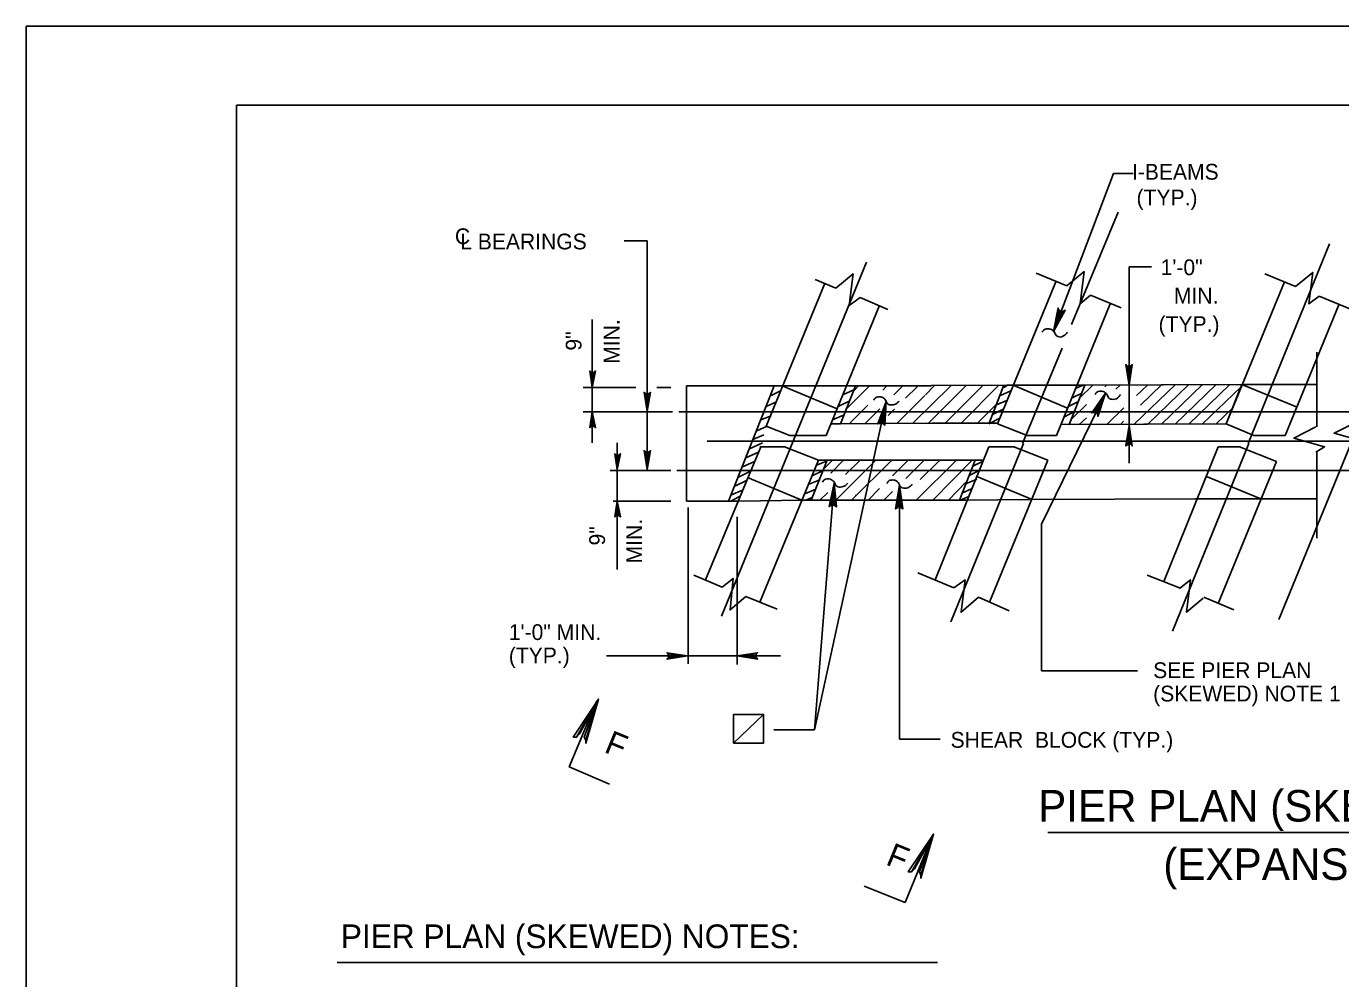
# Model space of a CAD drawing. Extents: x 638091 to 638946, y 298288 to 298882.
# Drawn here: x 638090.6 to 638340.6, y 298700.4 to 298881.5 of the extents above; entities that cross this region are included whole.
import ezdxf

# ---------------------------------------------------------------- set-up
doc = ezdxf.new("R2010")
doc.units = 0
for name, color, linetype in [('1', 7, 'Continuous'), ('2', 7, 'Continuous'), ('PLT-BNDY', 7, 'Continuous')]:
    doc.layers.add(name, color=color, linetype=linetype)

msp = doc.modelspace()

# ---------------------------------------------------------------- linework, layer by layer
at = {"layer": '1'}
for p, q in [((638290.98, 298810.87), (638293.45, 298813.25)), ((638295.72, 298812.94), (638296.06, 298813.27)), ((638297.84, 298812.49), (638298.66, 298813.28)), ((638301.29, 298805.81), (638309.08, 298813.33)), ((638301.75, 298811.26), (638303.87, 298813.31)), ((638302.48, 298809.46), (638306.48, 298813.32)), ((638303.9, 298805.82), (638311.69, 298813.35)), ((638306.5, 298805.83), (638314.29, 298813.36)), ((638309.1, 298805.85), (638316.9, 298813.37)), ((638311.71, 298805.86), (638319.5, 298813.38)), ((638314.31, 298805.87), (638321.58, 298812.89)), ((638240.51, 298747.71), (638254.12, 298810.14)), ((638289.35, 298806.79), (638292.22, 298809.56)), ((638296.08, 298805.78), (638299.34, 298808.93)), ((638316.92, 298805.89), (638319.95, 298808.82)), ((638290.87, 298805.76), (638292.21, 298807.05)), ((638298.69, 298805.79), (638299.3, 298806.39)), ((638244.27, 298794.62), (638240.51, 298747.71))]:
    msp.add_line(p, q, dxfattribs=at)
for points in [[(638291.93, 298813.25), (638288.93, 298805.75), (638318.78, 298805.9), (638321.78, 298813.4)], [(638225.11, 298745.15), (638230.77, 298745.15), (638230.77, 298750.63), (638225.11, 298750.63)], [(638225.11, 298745.15), (638230.77, 298750.63), (638230.77, 298745.15)]]:
    msp.add_lwpolyline(points, close=True, dxfattribs=at)
at = {"layer": '2'}
for p, q in [((638130.58, 298302.5), (638130.58, 298866.5)), ((638130.58, 298866.5), (638916.58, 298866.5)), ((638328.83, 298768.7), (638365.58, 298858.55)), ((638297.34, 298853.53), (638285.93, 298823.45)), ((638301.09, 298853.53), (638297.34, 298853.53)), ((638289.38, 298824.8), (638298.24, 298846.18)), ((638204.33, 298840.7), (638208.68, 298840.7)), ((638208.68, 298808.3), (638208.68, 298840.7)), ((638322.98, 298802.15), (638338.43, 298840.1)), ((638236.13, 298801.85), (638250.38, 298836.65)), ((638300.33, 298813.25), (638300.33, 298835.74)), ((638304.57, 298835.74), (638300.33, 298835.74)), ((638231.33, 298805.45), (638242.43, 298832.45)), ((638244.53, 298831.7), (638240.63, 298833.35)), ((638275.28, 298805.9), (638286.38, 298832.9)), ((638288.48, 298832.15), (638282.63, 298834.55)), ((638318.78, 298805.9), (638329.88, 298832.9)), ((638331.98, 298832), (638326.13, 298834.4)), ((638254.43, 298827.65), (638249.18, 298829.9)), ((638298.83, 298827.95), (638292.98, 298830.35)), ((638343.38, 298827.35), (638336.48, 298830.2)), ((638252.78, 298828.25), (638242.73, 298803.65)), ((638296.73, 298828.7), (638286.53, 298803.65)), ((638340.23, 298828.55), (638330.03, 298803.65)), ((638198.24, 298812.95), (638198.24, 298825.75)), ((638280.08, 298802.15), (638287.58, 298820.3)), ((638336.03, 298805.3), (638336.03, 298819.55)), ((638196.47, 298812.8), (638206.51, 298812.8)), ((638198.24, 298808.15), (638198.24, 298812.95)), ((638210.52, 298812.8), (638213.18, 298812.8)), ((638216.18, 298791.2), (638216.18, 298813.1)), ((638235.08, 298813.1), (638216.18, 298813.1)), ((638224.13, 298791.2), (638232.83, 298813.1)), ((638232.23, 298811.3), (638234.03, 298812.2)), ((638244.83, 298808.75), (638234.33, 298813.1)), ((638246.93, 298813.1), (638234.78, 298813.1)), ((638245.43, 298805.9), (638248.28, 298813.1)), ((638246.03, 298811.45), (638247.98, 298812.35)), ((638246.48, 298808.6), (638250.98, 298813.1)), ((638246.48, 298813.1), (638262.7, 298813.1)), ((638247.98, 298812.2), (638248.88, 298813.1)), ((638253.49, 298812.3), (638254.28, 298813.1)), ((638255.6, 298811.42), (638257.28, 298813.1)), ((638257.81, 298810.77), (638260.06, 298813.02)), ((638259.22, 298806.03), (638266.43, 298813.1)), ((638261.59, 298811.4), (638263.28, 298813.1)), ((638262.17, 298805.99), (638269.43, 298813.25)), ((638262.78, 298813.18), (638277.08, 298813.25)), ((638265.38, 298806.05), (638272.58, 298813.25)), ((638268.38, 298806.05), (638275.58, 298813.25)), ((638276.48, 298813.25), (638273.69, 298806.04)), ((638277.83, 298812.2), (638275.88, 298811.3)), ((638277.23, 298813.25), (638276.48, 298812.8)), ((638277.08, 298813.25), (638278.28, 298813.25)), ((638291.78, 298813.25), (638278.28, 298813.25)), ((638288.63, 298808.9), (638278.28, 298813.25)), ((638288.93, 298805.75), (638291.93, 298813.25)), ((638291.63, 298813.25), (638290.28, 298812.65)), ((638290.73, 298813.25), (638322.23, 298813.4)), ((638300.33, 298805.6), (638300.33, 298813.25)), ((638332.28, 298809.05), (638321.78, 298813.4)), ((638334.38, 298813.4), (638322.23, 298813.4)), ((638336.03, 298813.4), (638334.08, 298813.4)), ((638231.33, 298809.2), (638233.28, 298810.1)), ((638244.98, 298809.2), (638247.23, 298810.25)), ((638256.23, 298806.05), (638261.5, 298811.31)), ((638277.23, 298810.4), (638275.13, 298809.5)), ((638283.67, 298786.82), (638295.85, 298811.72)), ((638288.78, 298809.2), (638290.58, 298810.1)), ((638291.33, 298811.75), (638289.53, 298810.85)), ((638196.47, 298808.15), (638213.48, 298808.15)), ((638198.24, 298808.45), (638198.24, 298808.45)), ((638198.24, 298802.3), (638198.24, 298808.15)), ((638208.68, 298797.2), (638208.68, 298808.3)), ((638214.67, 298808.15), (638343.68, 298808.15)), ((638232.23, 298807.4), (638230.28, 298806.65)), ((638246.03, 298807.55), (638243.93, 298806.65)), ((638247.08, 298805.9), (638250.64, 298809.45)), ((638250.08, 298805.9), (638252.91, 298808.73)), ((638254.52, 298807.48), (638255.73, 298808.69)), ((638271.53, 298806.05), (638275.13, 298809.65)), ((638276.48, 298808.75), (638274.38, 298807.7)), ((638288.03, 298807.25), (638289.83, 298808.15)), ((638229.53, 298804.55), (638231.48, 298805.45)), ((638235.83, 298803.65), (638231.33, 298805.45)), ((638243.78, 298805.9), (638262.96, 298805.99)), ((638243.93, 298805.9), (638245.43, 298805.9)), ((638262.9, 298805.99), (638275.28, 298806.05)), ((638275.73, 298806.95), (638273.63, 298805.9)), ((638280.98, 298803.65), (638275.28, 298805.9)), ((638287.39, 298805.75), (638318.78, 298805.9)), ((638300.33, 298798.4), (638300.33, 298805.6)), ((638324.03, 298803.65), (638318.78, 298805.9)), ((638202.98, 298790.3), (638202.98, 298802.3)), ((638220.08, 298802.6), (638343.68, 298802.6)), ((638222.78, 298769.3), (638236.43, 298802.6)), ((638228.03, 298801.1), (638230.58, 298802.3)), ((638228.78, 298802.9), (638230.88, 298803.8)), ((638235.83, 298803.65), (638242.73, 298803.65)), ((638280.98, 298803.65), (638286.53, 298803.65)), ((638324.03, 298803.65), (638330.03, 298803.65)), ((638219.78, 298776.2), (638230.28, 298801.55)), ((638227.43, 298799.45), (638229.83, 298800.5)), ((638230.13, 298801.55), (638234.93, 298801.55)), ((638234.78, 298801.55), (638241.23, 298799)), ((638263.43, 298776.2), (638273.63, 298801.55)), ((638266.43, 298768.25), (638280.23, 298802.15)), ((638273.63, 298801.55), (638278.58, 298801.55)), ((638278.43, 298801.55), (638284.88, 298799)), ((638306.93, 298775.9), (638317.28, 298801.55)), ((638308.58, 298766.45), (638323.13, 298802.15)), ((638317.28, 298801.55), (638321.48, 298801.55)), ((638321.33, 298801.55), (638328.38, 298798.7)), ((638336.03, 298784.15), (638336.03, 298800.65)), ((638202.98, 298797.2), (638202.98, 298797.2)), ((638226.68, 298797.65), (638229.08, 298798.7)), ((638241.23, 298799), (638230.13, 298772)), ((638239.88, 298791.35), (638242.88, 298799)), ((638240.78, 298797.95), (638242.88, 298798.85)), ((638241.23, 298799), (638262.43, 298798.99)), ((638242.28, 298797.35), (638243.93, 298799)), ((638243.61, 298796.5), (638246.03, 298799)), ((638244.5, 298791.31), (638252.18, 298799)), ((638246.42, 298796.23), (638249.18, 298799)), ((638247.53, 298791.35), (638255.18, 298799)), ((638255.33, 298796), (638258.33, 298799)), ((638257.85, 298795.51), (638261.28, 298798.94)), ((638259.83, 298791.35), (638267.48, 298799)), ((638260.62, 298795.28), (638264.33, 298799)), ((638262.5, 298799), (638272.58, 298799)), ((638262.98, 298791.35), (638270.48, 298799)), ((638271.08, 298799), (638268.08, 298791.35)), ((638272.43, 298798.7), (638270.48, 298797.8)), ((638284.88, 298799), (638273.78, 298772)), ((638328.38, 298798.7), (638317.28, 298771.7)), ((638201.63, 298797.05), (638213.18, 298797.05)), ((638214.3, 298797.05), (638343.68, 298797.05)), ((638225.33, 298794.05), (638227.58, 298795.1)), ((638225.93, 298795.7), (638228.33, 298796.9)), ((638227.73, 298795.7), (638238.08, 298791.35)), ((638239.28, 298794.35), (638241.53, 298795.25)), ((638240.03, 298796), (638242.13, 298797.05)), ((638265.98, 298791.35), (638269.28, 298794.8)), ((638269.28, 298794.5), (638271.38, 298795.4)), ((638271.83, 298797.05), (638270.03, 298796.15)), ((638271.38, 298795.85), (638281.88, 298791.5)), ((638315.03, 298795.85), (638325.38, 298791.65)), ((638224.73, 298792.4), (638226.83, 298793.3)), ((638238.68, 298792.55), (638240.78, 298793.45)), ((638241.53, 298791.35), (638243.02, 298792.84)), ((638248.43, 298792.4), (638248.28, 298792.25)), ((638250.68, 298791.35), (638252.86, 298793.6)), ((638253.68, 298791.35), (638255.33, 298793)), ((638256.68, 298745.89), (638256.68, 298794.2)), ((638270.48, 298793.6), (638268.53, 298792.7)), ((638202.23, 298791.2), (638213.18, 298791.2)), ((638202.98, 298778.19), (638202.98, 298791.2)), ((638216.18, 298791.2), (638225.93, 298791.2)), ((638216.48, 298760.26), (638216.48, 298790)), ((638224.58, 298791.2), (638226.23, 298792.1)), ((638226.23, 298791.2), (638238.23, 298791.35)), ((638238.23, 298791.35), (638269.73, 298791.35)), ((638238.83, 298791.35), (638240.18, 298791.95)), ((638269.88, 298792.1), (638268.23, 298791.35)), ((638269.28, 298791.35), (638281.43, 298791.5)), ((638281.88, 298791.5), (638313.38, 298791.65)), ((638312.93, 298791.65), (638325.08, 298791.65)), ((638325.08, 298791.65), (638327.93, 298791.65)), ((638327.63, 298791.65), (638336.03, 298791.65)), ((638225.78, 298760.11), (638225.78, 298788.2)), ((638283.67, 298758.92), (638283.67, 298786.82)), ((638260.13, 298777.55), (638267.03, 298774.7)), ((638217.53, 298777.1), (638222.93, 298774.85)), ((638303.78, 298777.1), (638309.93, 298774.7)), ((638227.43, 298773.05), (638233.43, 298770.65)), ((638271.68, 298772.9), (638277.53, 298770.35)), ((638314.58, 298772.9), (638320.28, 298770.5)), ((638200.96, 298761.76), (638216.33, 298761.76)), ((638216.48, 298761.76), (638225.78, 298761.76)), ((638225.78, 298761.76), (638234.03, 298761.76)), ((638283.67, 298758.92), (638301.94, 298758.92)), ((638193.86, 298740.63), (638199.11, 298753.23)), ((638240.51, 298747.71), (638232.79, 298747.71)), ((638264.41, 298745.89), (638256.68, 298745.89)), ((638193.86, 298740.63), (638201.51, 298737.33)), ((638257.74, 298714.83), (638262.99, 298727.73)), ((638284.85, 298728.2), (638389.85, 298728.2)), ((638249.94, 298717.98), (638257.74, 298714.83)), ((638149.7, 298703.43), (638263.88, 298703.43))]:
    msp.add_line(p, q, dxfattribs=at)
for points in [[(638288.48, 298832.15), (638291.78, 298834.85), (638291.03, 298828.7), (638292.98, 298830.35)], [(638331.98, 298832), (638335.28, 298834.7), (638334.53, 298828.7), (638336.48, 298830.2)], [(638244.53, 298831.7), (638247.83, 298834.4), (638247.08, 298828.4), (638249.18, 298829.9)], [(638286.83, 298827.65), (638287.13, 298827.5), (638285.93, 298823.45), (638286.83, 298827.65), (638286.83, 298827.95), (638285.93, 298823.45), (638287.58, 298827.2), (638287.88, 298827.35), (638285.93, 298823.45), (638288.18, 298827.5), (638287.88, 298827.35)], [(638198.69, 298815.8), (638198.39, 298815.65), (638198.24, 298812.8), (638198.69, 298815.8), (638198.84, 298815.95), (638198.24, 298812.8), (638198.09, 298815.65), (638197.94, 298815.8), (638198.24, 298812.8), (638197.79, 298815.95), (638197.94, 298815.8)], [(638300.78, 298817), (638300.48, 298816.85), (638300.33, 298813.25), (638300.78, 298817), (638300.93, 298817.15), (638300.33, 298813.25), (638300.18, 298816.85), (638299.88, 298816.85), (638300.33, 298813.25), (638299.73, 298817.15), (638299.88, 298816.85)], [(638209.13, 298811.75), (638208.83, 298811.6), (638208.68, 298808.3), (638209.13, 298811.75), (638209.28, 298811.9), (638208.68, 298808.3), (638208.53, 298811.6), (638208.23, 298811.75), (638208.68, 298808.3), (638208.08, 298811.9), (638208.23, 298811.75)], [(638252.7, 298805.99), (638253.02, 298806.08), (638254.12, 298810.14), (638252.7, 298805.99), (638252.52, 298805.87), (638254.12, 298810.14), (638253.46, 298805.99), (638253.73, 298805.78), (638254.12, 298810.14), (638253.85, 298805.61), (638253.73, 298805.78)], [(638293.44, 298808.05), (638293.77, 298808.07), (638295.85, 298811.75), (638293.44, 298808.05), (638293.24, 298807.98), (638295.85, 298811.75), (638294.18, 298807.89), (638294.4, 298807.64), (638295.85, 298811.75), (638294.42, 298807.3), (638294.4, 298807.64)], [(638197.94, 298805.3), (638198.09, 298805.45), (638198.24, 298808.15), (638197.94, 298805.3), (638197.79, 298805.15), (638198.24, 298808.15), (638198.39, 298805.45), (638198.69, 298805.3), (638198.24, 298808.15), (638198.84, 298805.15), (638198.69, 298805.3)], [(638299.88, 298801.85), (638300.18, 298802), (638300.33, 298805.6), (638299.88, 298801.85), (638299.73, 298801.7), (638300.33, 298805.6), (638300.48, 298802), (638300.78, 298802), (638300.33, 298805.6), (638300.93, 298801.7), (638300.78, 298802)], [(638299.88, 298801.85), (638300.18, 298802), (638300.33, 298805.6), (638299.88, 298801.85), (638299.73, 298801.7), (638300.33, 298805.6), (638300.48, 298802), (638300.78, 298802), (638300.33, 298805.6), (638300.93, 298801.7), (638300.78, 298802)], [(638335.88, 298805.3), (638331.68, 298803.2), (638337.53, 298801.55), (638335.88, 298800.5)], [(638343.53, 298806.2), (638339.33, 298804.1), (638345.18, 298802.45), (638343.53, 298801.4)], [(638203.43, 298800.05), (638203.13, 298799.9), (638202.98, 298797.2), (638203.43, 298800.05), (638203.58, 298800.2), (638202.98, 298797.2), (638202.83, 298799.9), (638202.68, 298800.05), (638202.98, 298797.2), (638202.53, 298800.2), (638202.68, 298800.05)], [(638209.13, 298800.65), (638208.83, 298800.5), (638208.68, 298797.2), (638209.13, 298800.65), (638209.28, 298800.8), (638208.68, 298797.2), (638208.53, 298800.5), (638208.23, 298800.65), (638208.68, 298797.2), (638208.08, 298800.8), (638208.23, 298800.65)], [(638243.47, 298790.31), (638243.77, 298790.44), (638244.27, 298794.62), (638243.47, 298790.31), (638243.31, 298790.16), (638244.27, 298794.62), (638244.22, 298790.42), (638244.51, 298790.26), (638244.27, 298794.62), (638244.66, 298790.1), (638244.51, 298790.26)], [(638256.08, 298789.85), (638256.38, 298790), (638256.68, 298794.2), (638256.08, 298789.85), (638255.93, 298789.7), (638256.68, 298794.2), (638256.83, 298790), (638257.13, 298789.85), (638256.68, 298794.2), (638257.28, 298789.7), (638257.13, 298789.85)], [(638202.68, 298788.35), (638202.98, 298788.5), (638202.98, 298791.2), (638202.68, 298788.35), (638202.53, 298788.2), (638202.98, 298791.2), (638203.13, 298788.5), (638203.43, 298788.35), (638202.98, 298791.2), (638203.58, 298788.2), (638203.43, 298788.35)], [(638227.43, 298773.05), (638224.43, 298770.5), (638225.03, 298776.5), (638222.93, 298774.85)], [(638271.68, 298772.9), (638268.38, 298770.05), (638269.13, 298776.2), (638267.03, 298774.7)], [(638314.43, 298772.75), (638311.28, 298770.05), (638312.03, 298776.2), (638309.93, 298774.55)], [(638212.58, 298762.21), (638212.73, 298761.91), (638216.33, 298761.76), (638212.58, 298762.21), (638212.43, 298762.36), (638216.33, 298761.76), (638212.73, 298761.61), (638212.73, 298761.31), (638216.33, 298761.76), (638212.43, 298761.16), (638212.73, 298761.31)], [(638229.53, 298761.31), (638229.38, 298761.61), (638225.78, 298761.76), (638229.53, 298761.31), (638229.68, 298761.16), (638225.78, 298761.76), (638229.38, 298761.91), (638229.38, 298762.21), (638225.78, 298761.76), (638229.68, 298762.36), (638229.38, 298762.21)], [(638229.53, 298761.31), (638229.38, 298761.61), (638225.78, 298761.76), (638229.53, 298761.31), (638229.68, 298761.16), (638225.78, 298761.76), (638229.38, 298761.91), (638229.38, 298762.21), (638225.78, 298761.76), (638229.68, 298762.36), (638229.38, 298762.21)], [(638195.21, 298746.33), (638195.81, 298746.93), (638199.41, 298753.53), (638195.21, 298746.33), (638194.61, 298746.33), (638199.41, 298753.53), (638196.71, 298746.33), (638197.01, 298745.73), (638199.41, 298753.53), (638197.01, 298745.13), (638197.01, 298745.73)], [(638258.94, 298720.68), (638259.54, 298721.28), (638263.14, 298727.88), (638258.94, 298720.68), (638258.34, 298720.68), (638263.14, 298727.88), (638260.44, 298720.68), (638260.74, 298720.08), (638263.14, 298727.88), (638260.74, 298719.48), (638260.74, 298720.08)]]:
    msp.add_lwpolyline(points, dxfattribs=at)
for points in [[(638288.63, 298823.3), (638288.18, 298822.85), (638287.28, 298822.4), (638286.38, 298822.85), (638286.08, 298823.45), (638285.33, 298823.9), (638284.43, 298823.9), (638284.13, 298823.75), (638283.83, 298823.3)], [(638256.58, 298810.23), (638256.13, 298809.78), (638255.23, 298809.48), (638254.33, 298809.78), (638254.03, 298810.38), (638253.28, 298810.98), (638252.38, 298810.98), (638252.08, 298810.83), (638251.78, 298810.38)], [(638298.68, 298811.45), (638298.38, 298811), (638297.33, 298810.55), (638296.43, 298810.85), (638296.13, 298811.45), (638295.38, 298812.05), (638294.48, 298812.05), (638294.18, 298811.9), (638293.88, 298811.45)], [(638246.82, 298794.62), (638246.37, 298794.17), (638245.47, 298793.87), (638244.57, 298794.17), (638244.27, 298794.77), (638243.52, 298795.37), (638242.62, 298795.37), (638242.32, 298795.22), (638242.02, 298794.77)], [(638259.09, 298794.4), (638258.64, 298793.95), (638257.74, 298793.65), (638256.84, 298793.95), (638256.54, 298794.55), (638255.79, 298795.15), (638254.89, 298795.15), (638254.59, 298795), (638254.29, 298794.55)]]:
    msp.add_spline(points, degree=3, dxfattribs=at)
at = {"layer": 'PLT-BNDY'}
msp.add_lwpolyline([(638090.58, 298287.5), (638931.58, 298287.5), (638931.58, 298881.5), (638090.58, 298881.5)], close=True, dxfattribs=at)

# ---------------------------------------------------------------- texts
at = {"layer": '2'}
for s, height, p in [(' I-BEAMS', 3, (638299.76, 298852.33)), (' (TYP.)', 3, (638300.64, 298847.46)), ('C', 3, (638172.11, 298840.07)), ('L BEARINGS ', 2.9999, (638173.11, 298839.07)), ('1\'-0"', 3, (638306.33, 298834.17)), ('MIN.', 3, (638308.86, 298828.77)), ('(TYP.)', 3, (638305.94, 298823.37)), ('1\'-0" MIN.', 3, (638182.36, 298764.78)), ('(TYP.)', 3, (638182.36, 298760.34)), ('SEE PIER PLAN', 2.9999, (638304.91, 298757.53)), ('(SKEWED) NOTE 1', 2.9999, (638304.91, 298753.09)), ('SHEAR  BLOCK (TYP.)', 2.9999, (638266.38, 298744.29)), (' PIER PLAN (SKEWED)', 5.9998, (638280.8, 298730.25)), ('(EXPANSION)', 5.9998, (638306.84, 298719.14)), ('PIER PLAN (SKEWED) NOTES:', 4.5, (638150.41, 298706.18))]:
    msp.add_text(s, height=height, dxfattribs=at).set_placement(p)
for s, height, rotation, p in [('MIN.', 3, 90, (638203.42, 298817.32)), ('9"', 3, 90, (638196.19, 298819.82)), ('MIN.', 3, 90, (638207.71, 298779.35)), ('9"', 3, 90, (638200.66, 298782.76)), ('F', 4.5, 337.7726, (638200.29, 298743.52)), ('F', 4.5, 337.7903, (638253.85, 298722.15))]:
    msp.add_text(s, height=height, rotation=rotation, dxfattribs=at).set_placement(p)

doc.saveas('drawing.dxf')
